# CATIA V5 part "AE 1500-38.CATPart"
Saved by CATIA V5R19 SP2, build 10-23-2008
Part number: BS 1500-38
Bounding box of the stored display mesh (mm): x -37.351 to 37.351, y -37.351 to 37.351, z 0 to 136
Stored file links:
  C:\Users\Bora\Desktop\3D Katı model\AE serisi\AE 1500\BS 1500-38.CATPart
  C:\Program Files\Dassault Systemes\B19\intel_a\reffiles\standard\MetricThickPitch.txt
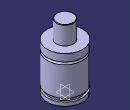
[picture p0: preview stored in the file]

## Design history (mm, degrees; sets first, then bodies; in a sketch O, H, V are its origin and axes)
Body1 (main body)
  Sketch1 on yz-plane, origin (0, 0, 0), H (0, 1, 0), V (0, 0, 1)
    point P1 (37.5, 81.5)
    point P5 (18, 135)
    point P7 (18, 135)
    point P12 (37.5, 76.5)
    point P13 (37.5, 81.5)
    point P14 (37.5, 76.5)
    line L1 (37.5, 81.5) -> (37.5, 97)
    line L2 (37.5, 0) -> (37.5, 8)
    arc A1 centre (17, 135) radius 1 from (18, 135) to (17, 136) ccw
    line L3 (18, 135) -> (18, 97)
    line L4 (33.5, 15) -> (33.5, 8)
    line L5 (37.5, 15) -> (37.5, 76.5)
    arc A2 centre (37.5, 79) radius 2.5 from (37.5, 81.5) to (37.5, 76.5) ccw
    line L6 (17, 136) -> (0, 136)
    point P15 (0, 136)
    line L7 (18, 97) -> (37.5, 97)
    line L8 (0, 0) -> (37.5, 0)
    line L9 (33.5, 15) -> (37.5, 15)
    line L10 (33.5, 8) -> (37.5, 8)
    coincidence: P15 V, P1 P13, P5 P7, P12 P14
    tangency: L6 A1
    horizontal: L7 H, L8 H, L9 H, L10 H
  Shaft1: profile Sketch1, axis Sketch1.V, angle 360
  Sketch2 on face of Shaft1 from Sketch1.L8, origin (0, 0, 0), H (1, 0, 0), V (0, -1, 0)
    point P1 (20, 0)
    distance P1 V = 20
  Hole1: placed by Sketch2, at (20, 0, 0) direction (0, 0, 1), diameter 6.647, depth 13, threaded "M8", thread diameter 8, thread depth 13, pitch 1.25
  CircPattern1: of Hole1, instances 4, angular step 90, axis from xy-plane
